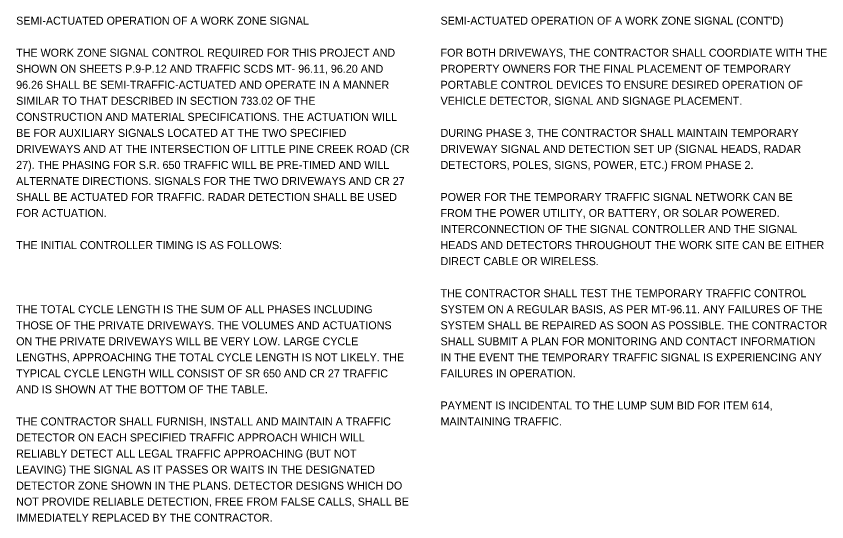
# Model space of a CAD drawing. Extents: x -18.6 to 34, y -8.1 to 37.1.
# Drawn here: x 2.4 to 16.57, y 28.32 to 37.15 of the extents above; entities that cross this region are included whole.
import ezdxf

# ---------------------------------------------------------------- set-up
doc = ezdxf.new("R2010")
doc.units = 0
doc.layers.add('Default', color=7, linetype='Continuous')

msp = doc.modelspace()

# ---------------------------------------------------------------- texts
at = {"layer": 'Default'}
for s, p in [('SEMI-ACTUATED OPERATION OF A WORK ZONE SIGNAL', (2.4, 37)), ("SEMI-ACTUATED OPERATION OF A WORK ZONE SIGNAL (CONT'D)", (9.82, 37)), ('THE WORK ZONE SIGNAL CONTROL REQUIRED FOR THIS PROJECT AND ', (2.4, 36.44)), ('FOR BOTH DRIVEWAYS, THE CONTRACTOR SHALL COORDIATE WITH THE ', (9.82, 36.44)), ('SHOWN ON SHEETS P.9-P.12 AND TRAFFIC SCDS MT- 96.11, 96.20 AND ', (2.4, 36.16)), ('PROPERTY OWNERS FOR THE FINAL PLACEMENT OF TEMPORARY ', (9.82, 36.16)), ('96.26 SHALL BE SEMI-TRAFFIC-ACTUATED AND OPERATE IN A MANNER ', (2.4, 35.88)), ('PORTABLE CONTROL DEVICES TO ENSURE DESIRED OPERATION OF ', (9.82, 35.88)), ('SIMILAR TO THAT DESCRIBED IN SECTION 733.02 OF THE ', (2.4, 35.6)), ('VEHICLE DETECTOR, SIGNAL AND SIGNAGE PLACEMENT. ', (9.82, 35.6)), ('CONSTRUCTION AND MATERIAL SPECIFICATIONS. THE ACTUATION WILL ', (2.4, 35.32)), ('BE FOR AUXILIARY SIGNALS LOCATED AT THE TWO SPECIFIED ', (2.4, 35.04)), ('DURING PHASE 3, THE CONTRACTOR SHALL MAINTAIN TEMPORARY ', (9.82, 35.04)), ('DRIVEWAYS AND AT THE INTERSECTION OF LITTLE PINE CREEK ROAD (CR ', (2.4, 34.76)), ('DRIVEWAY SIGNAL AND DETECTION SET UP (SIGNAL HEADS, RADAR ', (9.82, 34.76)), ('27). THE PHASING FOR S.R. 650 TRAFFIC WILL BE PRE-TIMED AND WILL ', (2.4, 34.48)), ('DETECTORS, POLES, SIGNS, POWER, ETC.) FROM PHASE 2. ', (9.82, 34.48)), ('ALTERNATE DIRECTIONS. SIGNALS FOR THE TWO DRIVEWAYS AND CR 27 ', (2.4, 34.2)), ('SHALL BE ACTUATED FOR TRAFFIC. RADAR DETECTION SHALL BE USED ', (2.4, 33.92)), ('POWER FOR THE TEMPORARY TRAFFIC SIGNAL NETWORK CAN BE ', (9.82, 33.92)), ('FOR ACTUATION.', (2.4, 33.64)), ('FROM THE POWER UTILITY, OR BATTERY, OR SOLAR POWERED. ', (9.82, 33.64)), ('INTERCONNECTION OF THE SIGNAL CONTROLLER AND THE SIGNAL ', (9.82, 33.36)), ('THE INITIAL CONTROLLER TIMING IS AS FOLLOWS:', (2.4, 33.08)), ('HEADS AND DETECTORS THROUGHOUT THE WORK SITE CAN BE EITHER ', (9.82, 33.08)), ('DIRECT CABLE OR WIRELESS. ', (9.82, 32.8)), ('THE CONTRACTOR SHALL TEST THE TEMPORARY TRAFFIC CONTROL ', (9.82, 32.24)), ('THE TOTAL CYCLE LENGTH IS THE SUM OF ALL PHASES INCLUDING ', (2.4, 31.96)), ('SYSTEM ON A REGULAR BASIS, AS PER MT-96.11. ANY FAILURES OF THE ', (9.82, 31.96)), ('THOSE OF THE PRIVATE DRIVEWAYS. THE VOLUMES AND ACTUATIONS ', (2.4, 31.68)), ('SYSTEM SHALL BE REPAIRED AS SOON AS POSSIBLE. THE CONTRACTOR ', (9.82, 31.68)), ('ON THE PRIVATE DRIVEWAYS WILL BE VERY LOW. LARGE CYCLE ', (2.4, 31.4)), ('SHALL SUBMIT A PLAN FOR MONITORING AND CONTACT INFORMATION ', (9.82, 31.4)), ('LENGTHS, APPROACHING THE TOTAL CYCLE LENGTH IS NOT LIKELY. THE ', (2.4, 31.12)), ('IN THE EVENT THE TEMPORARY TRAFFIC SIGNAL IS EXPERIENCING ANY ', (9.82, 31.12)), ('TYPICAL CYCLE LENGTH WILL CONSIST OF SR 650 AND CR 27 TRAFFIC ', (2.4, 30.84)), ('FAILURES IN OPERATION.', (9.82, 30.84)), ('AND IS SHOWN AT THE BOTTOM OF THE TABLE. ', (2.4, 30.56)), ('PAYMENT IS INCIDENTAL TO THE LUMP SUM BID FOR ITEM 614, ', (9.82, 30.28)), ('THE CONTRACTOR SHALL FURNISH, INSTALL AND MAINTAIN A TRAFFIC ', (2.4, 30)), ('MAINTAINING TRAFFIC.', (9.82, 30)), ('DETECTOR ON EACH SPECIFIED TRAFFIC APPROACH WHICH WILL ', (2.4, 29.72)), ('RELIABLY DETECT ALL LEGAL TRAFFIC APPROACHING (BUT NOT ', (2.4, 29.44)), ('LEAVING) THE SIGNAL AS IT PASSES OR WAITS IN THE DESIGNATED ', (2.4, 29.16)), ('DETECTOR ZONE SHOWN IN THE PLANS. DETECTOR DESIGNS WHICH DO ', (2.4, 28.88)), ('NOT PROVIDE RELIABLE DETECTION, FREE FROM FALSE CALLS, SHALL BE ', (2.4, 28.6)), ('IMMEDIATELY REPLACED BY THE CONTRACTOR. ', (2.4, 28.32))]:
    msp.add_text(s, height=0.14, dxfattribs=at).set_placement(p)

doc.saveas('drawing.dxf')
